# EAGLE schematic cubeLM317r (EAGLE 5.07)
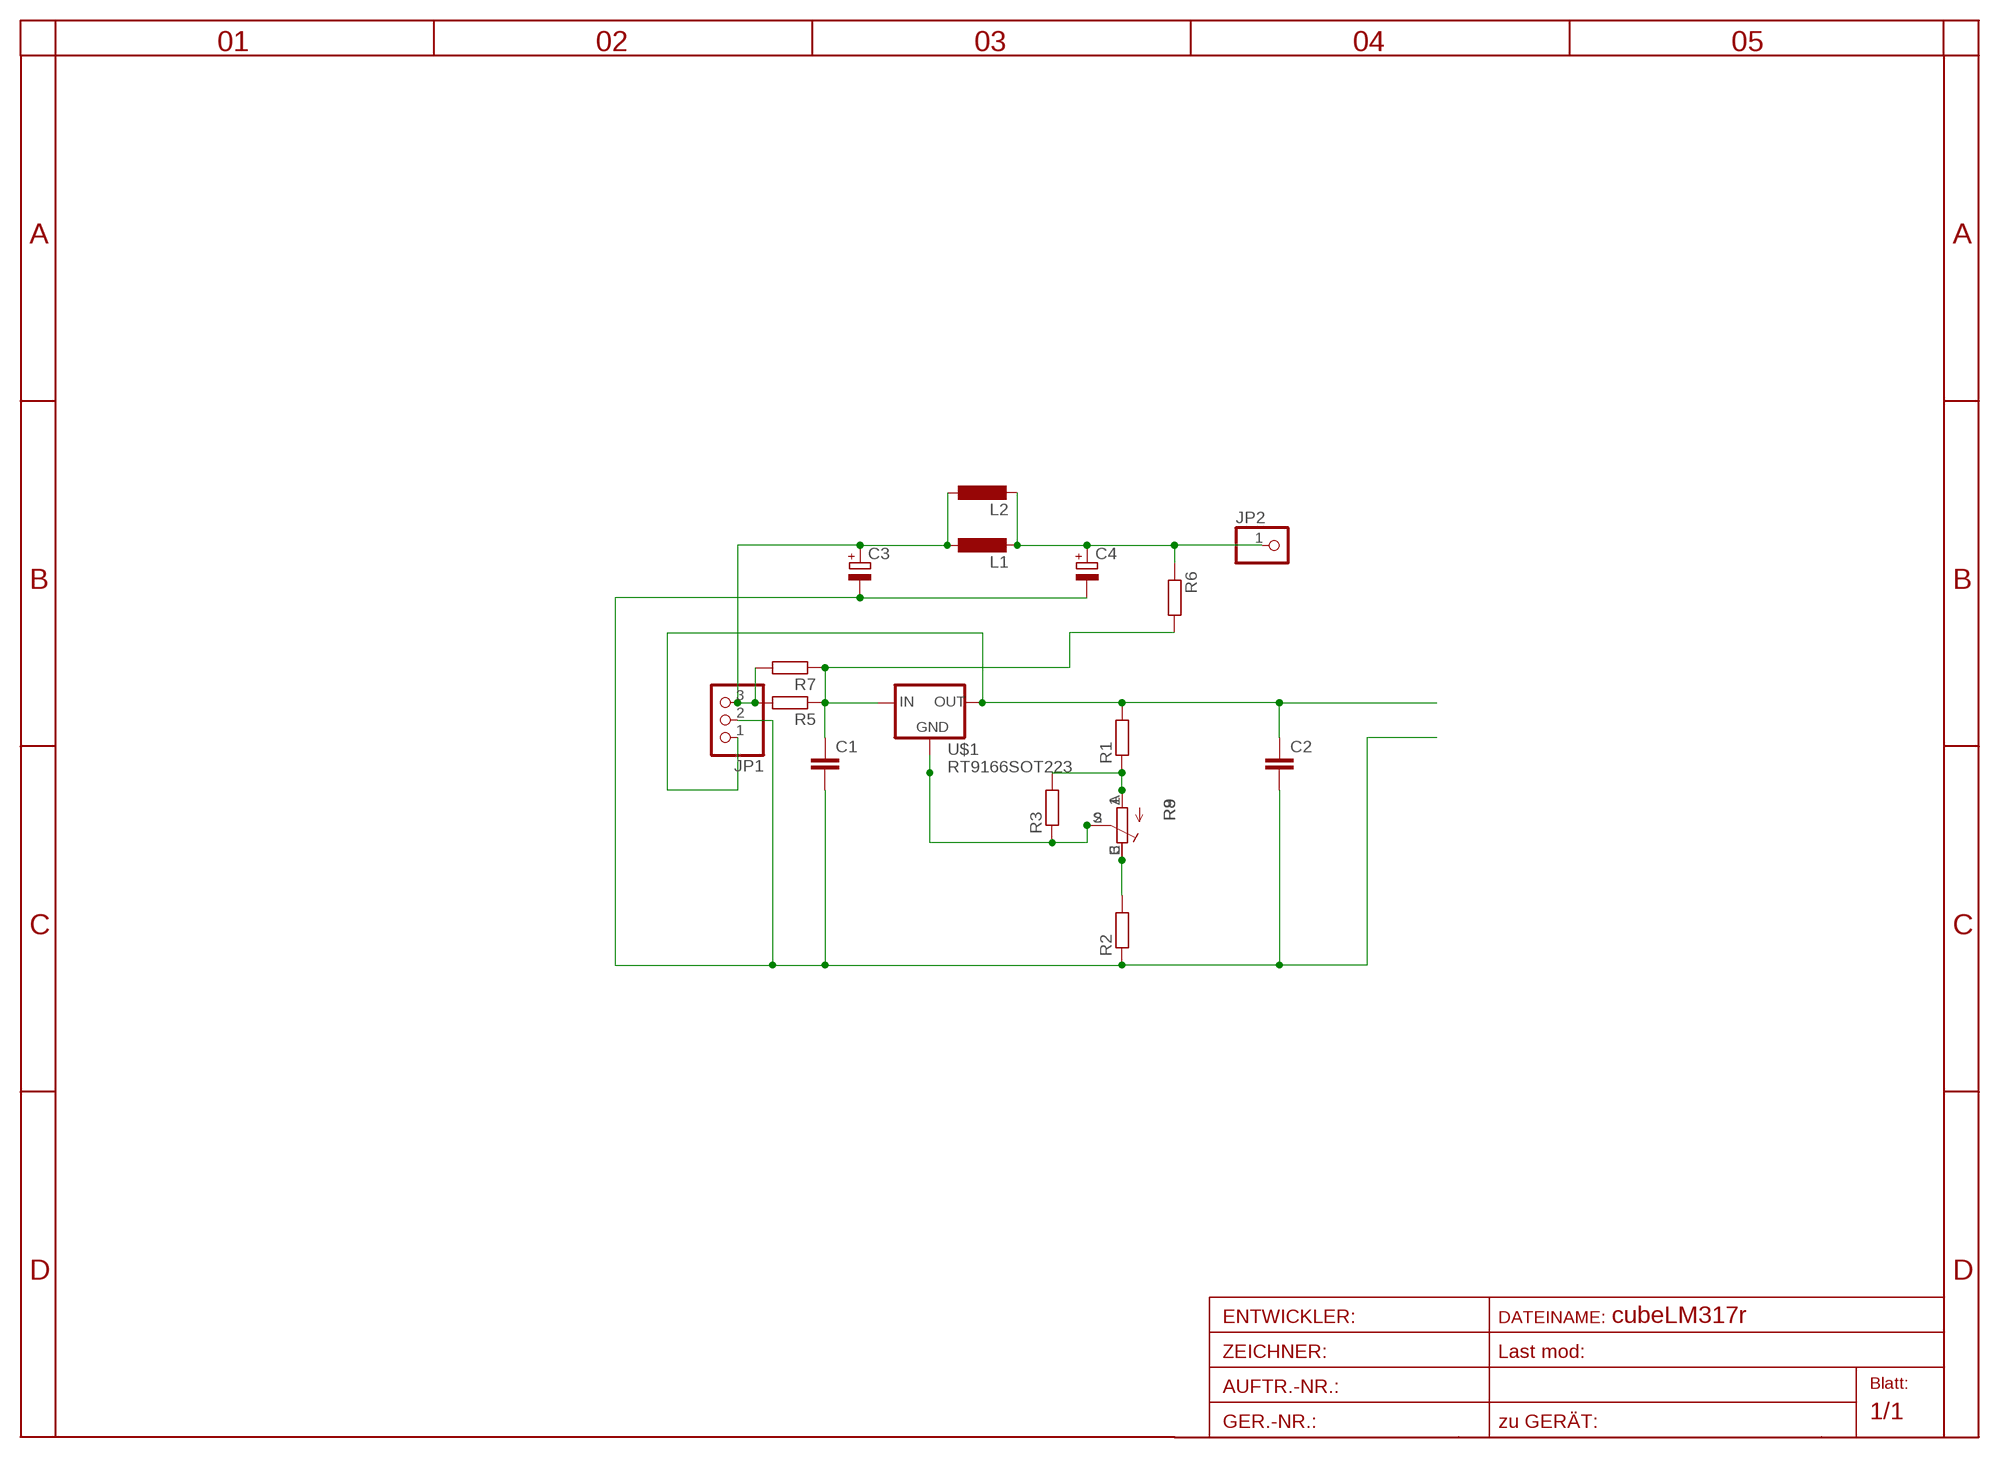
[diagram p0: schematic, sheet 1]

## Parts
C1  C-EUC1206  [C1206]
C2  C-EUC1206  [C1206]
C3  CPOL-EUE  [PANASONIC_E]
C4  CPOL-EUE  [PANASONIC_E]
JP1  PINHD-1X3  [1X03]
JP2  PINHD-1X11X0.4  [1X01]
L1  L-EUPIS2816  [PIS2816]
L2  L-EUOPEN  [OPEN5]
R1  R-EU_R0805  [R0805]
R2  R-EU_R0805  [R0805]
R3  R-EU_R0805  [R0805]
R5  R-EU_R0805  [R0805]
R6  R-EU_R0805  [R0805]
R7  R-EU_R0805  [R0805]
R8  TRIM_EU-RAND160  [RANDL]
R9  R-TRIMM3339P  [RTRIM3339P]
U$1  RT9166SOT223  [SOT223]

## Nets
ADJ: R3.1 R8.S R9.2(S) U$1.2(GND) U$1.4(GND1)
GND: C1.2 C2.2 C3.- C4.- JP1.2 R2.1
IN: C1.1 R5.1 R6.2 R7.1 U$1.3(IN)
N$1: C3.+ JP1.3 L1.1 L2.1 R5.2 R7.2
N$3: C4.+ JP2.1 L1.2 L2.2 R6.1
N$6: R2.2 R8.E R9.3(A)
N$7: R1.1 R3.2 R8.A R9.1(E)
OUT: C2.1 JP1.1 R1.2 U$1.1(OUT)

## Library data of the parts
C1 C2 = rcl:C-EU: CAPACITOR, European symbol
C3 C4 = rcl:CPOL-EU: POLARIZED CAPACITOR, European symbol
JP1 = pinhead:PINHD-1X3: PIN HEADER
JP2 = pinhead:PINHD-1X1: PIN HEADER
L1 L2 = rcl:L-EU: INDUCTOR, European symbol
R1-R3 R5-R7 = rcl:R-EU_: RESISTOR, European symbol
R8 = pot:TRIM_EU-: POTENTIOMETER
R9 = rcl:R-TRIMM: Trimm resistor
U$1 = v-reg:RT9166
